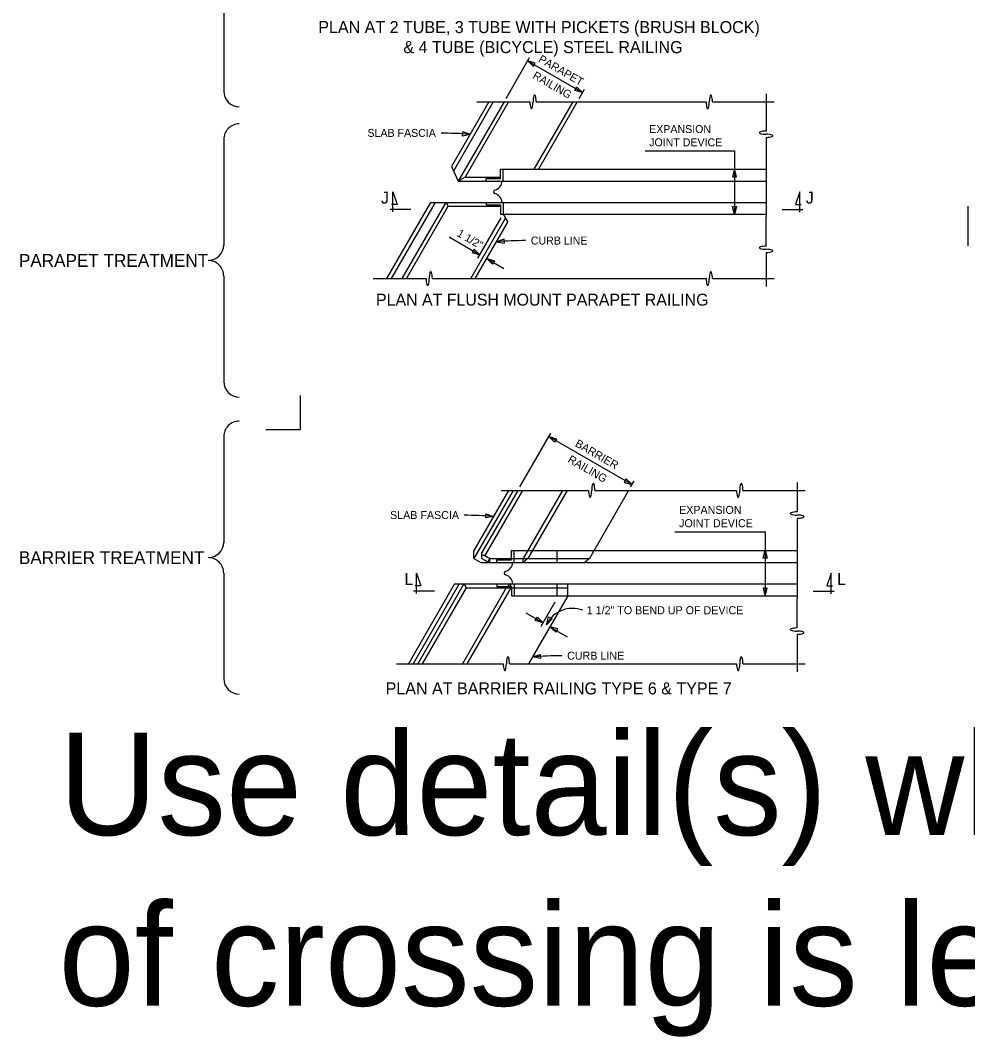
# Model space of a CAD drawing. Extents: x 19590 to 20151, y 19944 to 20103.
# Drawn here: x 19795.3 to 19850.6, y 19974.7 to 20034 of the extents above; entities that cross this region are included whole.
import ezdxf

# ---------------------------------------------------------------- set-up
doc = ezdxf.new("R2010")
doc.units = 0
for name, color, linetype in [('DETAIL_PR', 7, 'Continuous'), ('DETAIL_TEXT_DIMEN_PR', 7, 'Continuous'), ('Level 1', 7, 'Continuous')]:
    doc.layers.add(name, color=color, linetype=linetype)

msp = doc.modelspace()

# ---------------------------------------------------------------- linework, layer by layer
at = {"layer": 'DETAIL_PR'}
for p, q in [((19838.803, 20029.679), (19838.803, 20027.51)), ((19822.629, 20029.217), (19820.449, 20025.44)), ((19822.896, 20029.217), (19820.569, 20025.185)), ((19823.52, 20029.217), (19820.849, 20024.592)), ((19823.787, 20029.217), (19821.25, 20024.823)), ((19821.936, 20029.217), (19825.029, 20029.217)), ((19827.525, 20029.217), (19825.255, 20025.285)), ((19825.393, 20029.217), (19835.307, 20029.217)), ((19827.792, 20029.217), (19825.522, 20025.285)), ((19835.67, 20029.217), (19839.266, 20029.217)), ((19838.803, 20027.146), (19838.803, 20022.51)), ((19820.449, 20025.439), (19820.849, 20024.592)), ((19823.321, 20025.285), (19838.803, 20025.285)), ((19823.321, 20024.746), (19823.321, 20025.285)), ((19823.475, 20024.592), (19823.475, 20025.285)), ((19821.25, 20024.823), (19820.849, 20024.592)), ((19820.849, 20024.592), (19822.384, 20024.592)), ((19821.25, 20024.823), (19823.321, 20024.823)), ((19822.384, 20024.592), (19838.803, 20024.592)), ((19822.473, 20024.592), (19822.473, 20024.746)), ((19822.473, 20024.746), (19823.321, 20024.746)), ((19816.684, 20018.918), (19819.248, 20023.358)), ((19816.951, 20018.918), (19819.515, 20023.358)), ((19817.574, 20018.918), (19820.137, 20023.358)), ((19817.841, 20018.918), (19820.271, 20023.127)), ((19819.248, 20023.358), (19822.473, 20023.358)), ((19820.137, 20023.358), (19820.271, 20023.127)), ((19820.271, 20023.127), (19823.321, 20023.127)), ((19822.473, 20023.358), (19822.473, 20023.204)), ((19822.473, 20023.358), (19838.803, 20023.358)), ((19822.473, 20023.204), (19823.321, 20023.204)), ((19823.321, 20023.204), (19823.321, 20022.664)), ((19823.475, 20023.358), (19823.475, 20022.664)), ((19850.553, 20023.127), (19850.553, 20020.814)), ((19823.321, 20022.664), (19838.803, 20022.664)), ((19823.475, 20022.664), (19823.742, 20022.202)), ((19838.803, 20020.804), (19838.803, 20022.51)), ((19821.579, 20018.918), (19823.609, 20022.433)), ((19821.846, 20018.918), (19823.742, 20022.202)), ((19821.999, 20020.106), (19823.36, 20022.464)), ((19838.803, 20020.44), (19838.803, 20018.456)), ((19815.883, 20018.918), (19818.976, 20018.918)), ((19819.34, 20018.918), (19835.307, 20018.918)), ((19835.67, 20018.918), (19839.265, 20018.918)), ((19811.624, 20012.101), (19811.624, 20010.111)), ((19809.634, 20010.111), (19811.624, 20010.111)), ((19824.053, 20006.566), (19821.763, 20002.601)), ((19823.783, 20006.566), (19821.763, 20003.068)), ((19824.322, 20006.566), (19822.23, 20002.942)), ((19824.591, 20006.566), (19822.4, 20002.772)), ((19823.353, 20006.566), (19828.45, 20006.566)), ((19826.926, 20006.566), (19824.636, 20002.601)), ((19827.195, 20006.566), (19824.905, 20002.601)), ((19830.786, 20006.566), (19828.497, 20002.601)), ((19828.816, 20006.566), (19837.08, 20006.566)), ((19837.447, 20006.566), (19841.074, 20006.566)), ((19840.607, 20007.033), (19840.607, 20005.311)), ((19840.607, 20004.944), (19840.607, 20000.268)), ((19821.763, 20002.601), (19821.763, 20003.067)), ((19822.229, 20002.601), (19822.229, 20002.942)), ((19823.948, 20002.523), (19823.948, 20003.067)), ((19823.948, 20003.067), (19828.766, 20003.067)), ((19824.104, 20002.368), (19824.104, 20003.067)), ((19826.611, 20002.368), (19826.611, 20003.067)), ((19828.766, 20003.067), (19840.607, 20003.067)), ((19821.763, 20002.601), (19822.167, 20002.368)), ((19822.167, 20002.368), (19823.093, 20002.368)), ((19822.4, 20002.772), (19822.23, 20002.772)), ((19822.23, 20002.601), (19822.579, 20002.399)), ((19822.4, 20002.772), (19822.696, 20002.601)), ((19822.696, 20002.601), (19822.579, 20002.399)), ((19822.579, 20002.399), (19822.696, 20002.368)), ((19822.696, 20002.601), (19828.497, 20002.601)), ((19822.696, 20002.368), (19822.696, 20002.601)), ((19823.093, 20002.368), (19823.093, 20002.523)), ((19823.093, 20002.523), (19823.948, 20002.523)), ((19823.093, 20002.368), (19840.607, 20002.368)), ((19824.636, 20002.368), (19824.636, 20002.601)), ((19824.905, 20002.601), (19824.636, 20002.368)), ((19828.497, 20002.601), (19828.227, 20002.368)), ((19820.641, 20001.124), (19817.947, 19996.458)), ((19820.91, 20001.124), (19818.217, 19996.458)), ((19821.179, 20001.124), (19818.486, 19996.458)), ((19821.314, 20000.89), (19818.755, 19996.458)), ((19820.641, 20001.124), (19823.968, 20001.124)), ((19823.649, 20000.89), (19821.09, 19996.458)), ((19821.179, 20001.124), (19821.314, 20000.89)), ((19821.314, 20000.89), (19827.24, 20000.89)), ((19823.918, 20000.89), (19821.359, 19996.458)), ((19823.093, 20001.124), (19823.093, 20000.968)), ((19823.093, 20001.124), (19840.607, 20001.124)), ((19823.093, 20000.968), (19823.948, 20000.968)), ((19823.918, 20001.124), (19823.649, 20000.89)), ((19823.918, 20000.89), (19823.918, 20001.124)), ((19823.948, 20000.968), (19823.948, 20000.424)), ((19824.104, 20001.124), (19824.104, 20000.424)), ((19826.611, 20000.424), (19826.611, 20001.124)), ((19827.24, 20000.424), (19827.24, 20001.124)), ((19823.948, 20000.424), (19827.24, 20000.424)), ((19827.24, 20000.424), (19824.95, 19996.458)), ((19827.24, 20000.424), (19840.607, 20000.424)), ((19840.607, 19998.547), (19840.607, 20000.268)), ((19840.607, 19998.18), (19840.607, 19995.992)), ((19817.248, 19996.458), (19823.473, 19996.458)), ((19823.84, 19996.458), (19837.08, 19996.458)), ((19837.447, 19996.458), (19841.074, 19996.458))]:
    msp.add_line(p, q, dxfattribs=at)
for centre, radius, start, end in [((19822.799, 20024.656), 0.612, 288.13646, 353.93158), ((19822.997, 20023.975), 0.0999, 94.4387, 265.56132), ((19822.799, 20023.294), 0.612, 6.06842, 71.86353), ((19823.421, 20002.433), 0.618, 288.13646, 353.93158), ((19823.621, 20001.746), 0.101, 94.4387, 265.56132), ((19823.421, 20001.058), 0.618, 6.06842, 71.86353)]:
    msp.add_arc(centre, radius, start, end, dxfattribs=at)
for centre, major_axis, ratio, start_param, end_param in [((19825.302, 20029.217), (0, -0.395), 0.230204, 1.570796, 4.712389), ((19835.579, 20029.217), (0, -0.395), 0.230204, 1.570796, 4.712389), ((19825.12, 20029.217), (0, -0.395), 0.230206, 4.712389, 7.853982), ((19835.397, 20029.217), (0, -0.395), 0.230206, 4.712389, 7.853982), ((19838.803, 20027.419), (0.395, 0), 0.230204, 1.570796, 4.712389), ((19838.803, 20027.237), (0.395, 0), 0.230206, 4.712389, 7.853982), ((19838.803, 20020.713), (0.395, 0), 0.230204, 1.570796, 4.712389), ((19838.803, 20020.531), (0.395, 0), 0.230206, 4.712389, 7.853982), ((19819.249, 20018.918), (0, -0.395), 0.230204, 1.570796, 4.712389), ((19835.579, 20018.918), (0, -0.395), 0.230204, 1.570796, 4.712389), ((19819.067, 20018.918), (0, -0.395), 0.230206, 4.712389, 7.853982), ((19835.397, 20018.918), (0, -0.395), 0.230206, 4.712389, 7.853982), ((19828.541, 20006.566), (0, -0.398), 0.230206, 4.712389, 7.853982), ((19828.725, 20006.566), (0, -0.398), 0.230204, 1.570796, 4.712389), ((19837.172, 20006.566), (0, -0.398), 0.230206, 4.712389, 7.853982), ((19837.356, 20006.566), (0, -0.398), 0.230204, 1.570796, 4.712389), ((19840.607, 20005.22), (0.398, 0), 0.230204, 1.570796, 4.712389), ((19840.607, 20005.036), (0.398, 0), 0.230206, 4.712389, 7.853982), ((19840.607, 19998.455), (0.398, 0), 0.230204, 1.570796, 4.712389), ((19840.607, 19998.272), (0.398, 0), 0.230206, 4.712389, 7.853982), ((19823.565, 19996.458), (0, -0.398), 0.230206, 4.712389, 7.853982), ((19823.748, 19996.458), (0, -0.398), 0.230204, 1.570796, 4.712389), ((19837.172, 19996.458), (0, -0.398), 0.230206, 4.712389, 7.853982), ((19837.356, 19996.458), (0, -0.398), 0.230204, 1.570796, 4.712389)]:
    msp.add_ellipse(centre, major_axis=major_axis, ratio=ratio, start_param=start_param, end_param=end_param, dxfattribs=at)
at = {"layer": 'DETAIL_TEXT_DIMEN_PR'}
for p, q in [((19807.176, 20035.98), (19807.176, 20029.838)), ((19823.635, 20029.417), (19825.014, 20031.806)), ((19824.898, 20031.606), (19828.103, 20029.755)), ((19827.907, 20029.417), (19828.218, 20029.956)), ((19807.176, 20027.022), (19807.176, 20020.837)), ((19831.741, 20026.364), (19836.953, 20026.364)), ((19836.953, 20026.364), (19836.953, 20022.664)), ((19817.038, 20022.804), (19817.037, 20023.975)), ((19817.037, 20023.975), (19817.29, 20023.239)), ((19840.768, 20023.975), (19840.515, 20023.239)), ((19840.768, 20022.777), (19840.768, 20023.975)), ((19817.29, 20023.239), (19816.96, 20023.239)), ((19840.515, 20023.239), (19840.846, 20023.239)), ((19818.078, 20022.934), (19816.872, 20022.934)), ((19839.728, 20022.934), (19840.943, 20022.934)), ((19820.312, 20021.348), (19822.114, 20020.307)), ((19822.515, 20020.076), (19823.516, 20019.498)), ((19807.176, 20019.061), (19807.176, 20012.919)), ((19807.176, 20009.698), (19807.176, 20003.514)), ((19824.438, 20006.769), (19826.252, 20009.909)), ((19826.135, 20009.707), (19830.983, 20006.908)), ((19830.903, 20006.769), (19831.1, 20007.11)), ((19833.484, 20004.156), (19838.741, 20004.156)), ((19838.741, 20004.156), (19838.741, 20000.424)), ((19807.176, 20001.737), (19807.176, 19995.595)), ((19818.412, 20000.564), (19818.411, 20001.746)), ((19818.411, 20001.746), (19818.666, 20001.003)), ((19842.59, 20001.746), (19842.335, 20001.003)), ((19842.589, 20000.537), (19842.59, 20001.746)), ((19819.461, 20000.696), (19818.244, 20000.696)), ((19818.666, 20001.003), (19818.333, 20001.003)), ((19841.54, 20000.696), (19842.766, 20000.696)), ((19842.335, 20001.003), (19842.668, 20001.003)), ((19825.678, 19998.652), (19826.495, 20000.066)), ((19824.785, 19999.438), (19825.795, 19998.855)), ((19826.199, 19998.621), (19827.209, 19998.038))]:
    msp.add_line(p, q, dxfattribs=at)
for centre, radius, start, end in [((19808.086, 20029.839), 0.91, 180.03373, 270.03369), ((19808.086, 20027.022), 0.91, 89.96627, 180.03372), ((19819.112, 19988.252), 39.151, 86.44645, 88.92222), ((19806.266, 20020.881), 0.911, 269.96631, 359.96626), ((19825.511, 19981.986), 39.151, 91.07778, 93.55355), ((19806.266, 20019.061), 0.91, 359.96627, 90.03372), ((19808.086, 20012.92), 0.91, 180.03373, 270.03369), ((19808.086, 20009.699), 0.91, 89.96627, 180.03372), ((19820.46, 19965.634), 39.492, 86.44645, 88.92222), ((19806.266, 20003.558), 0.911, 269.96631, 359.96626), ((19806.266, 20001.737), 0.91, 359.96627, 90.03372), ((19827.511, 19998.012), 1.679, 69.13778, 154.38451), ((19827.631, 19957.446), 39.492, 91.07778, 93.55355), ((19808.086, 19995.596), 0.91, 180.03373, 270.03369)]:
    msp.add_arc(centre, radius, start, end, dxfattribs=at)
at = {"layer": 'Level 1'}
for p, q in [((19824.899, 20031.605), (19825.229, 20031.281)), ((19825.344, 20031.481), (19824.899, 20031.605)), ((19825.229, 20031.281), (19825.344, 20031.481)), ((19827.657, 20029.879), (19827.773, 20030.079)), ((19828.103, 20029.755), (19827.657, 20029.879)), ((19827.773, 20030.079), (19828.103, 20029.755)), ((19821.098, 20027.468), (19821.085, 20027.237)), ((19821.085, 20027.237), (19821.539, 20027.328)), ((19821.539, 20027.328), (19821.098, 20027.468)), ((19836.953, 20025.285), (19836.837, 20024.838)), ((19837.069, 20024.838), (19836.953, 20025.285)), ((19836.837, 20024.838), (19837.069, 20024.838)), ((19836.953, 20022.664), (19836.837, 20023.112)), ((19836.837, 20023.112), (19837.068, 20023.112)), ((19837.068, 20023.112), (19836.953, 20022.664)), ((19823.525, 20021.202), (19823.084, 20021.062)), ((19823.084, 20021.062), (19823.538, 20020.971)), ((19823.538, 20020.971), (19823.525, 20021.202)), ((19821.784, 20020.631), (19821.668, 20020.43)), ((19821.668, 20020.43), (19822.114, 20020.306)), ((19822.114, 20020.306), (19821.784, 20020.631)), ((19822.515, 20020.076), (19822.96, 20019.952)), ((19822.845, 20019.751), (19822.515, 20020.076)), ((19822.96, 20019.952), (19822.845, 20019.751)), ((19826.135, 20009.707), (19826.585, 20009.582)), ((19826.468, 20009.38), (19826.135, 20009.707)), ((19826.585, 20009.582), (19826.468, 20009.38)), ((19830.65, 20007.235), (19830.534, 20007.033)), ((19830.984, 20006.908), (19830.65, 20007.235)), ((19830.534, 20007.033), (19830.984, 20006.908)), ((19822.45, 20004.959), (19822.463, 20005.192)), ((19822.908, 20005.05), (19822.45, 20004.959)), ((19822.463, 20005.192), (19822.908, 20005.05)), ((19838.624, 20002.616), (19838.741, 20003.067)), ((19838.741, 20003.067), (19838.858, 20002.616)), ((19838.858, 20002.616), (19838.624, 20002.616)), ((19838.858, 20000.875), (19838.624, 20000.875)), ((19838.624, 20000.875), (19838.741, 20000.424)), ((19838.741, 20000.424), (19838.858, 20000.875)), ((19825.345, 19998.979), (19825.462, 19999.182)), ((19825.795, 19998.854), (19825.345, 19998.979)), ((19825.462, 19999.182), (19825.795, 19998.854)), ((19825.997, 19998.738), (19826.122, 19999.188)), ((19826.324, 19999.071), (19825.997, 19998.738)), ((19826.122, 19999.188), (19826.324, 19999.071)), ((19826.199, 19998.621), (19826.532, 19998.295)), ((19826.648, 19998.497), (19826.199, 19998.621)), ((19826.532, 19998.295), (19826.648, 19998.497)), ((19825.184, 19996.862), (19825.629, 19997.004)), ((19825.641, 19996.771), (19825.184, 19996.862)), ((19825.629, 19997.004), (19825.641, 19996.771))]:
    msp.add_line(p, q, dxfattribs=at)

# ---------------------------------------------------------------- texts
at = {"layer": 'DETAIL_TEXT_DIMEN_PR'}
for s, height, p in [('PLAN AT 2 TUBE, 3 TUBE WITH PICKETS (BRUSH BLOCK)', 0.69987, (19812.691, 20033.224)), (' & 4 TUBE (BICYCLE) STEEL RAILING', 0.69987, (19817.394, 20032.058)), ('EXPANSION ', 0.4625, (19831.982, 20027.398)), ('SLAB FASCIA', 0.4625, (19815.559, 20027.177)), ('JOINT DEVICE', 0.4625, (19831.982, 20026.627)), ('J', 0.694, (19816.343, 20023.282)), ('J', 0.694, (19841.115, 20023.281)), ('CURB LINE', 0.4625, (19825.083, 20020.899)), ('PLAN AT FLUSH MOUNT PARAPET RAILING', 0.69385, (19816.056, 20017.336)), ('SLAB FASCIA', 0.46653, (19816.875, 20004.898)), ('EXPANSION ', 0.4665, (19833.727, 20005.198)), ('JOINT DEVICE', 0.46653, (19833.727, 20004.421)), ('L', 0.7, (19817.712, 20001.046)), ('L', 0.7, (19842.94, 20001.046)), ('1 1/2" TO BEND UP OF DEVICE', 0.46653, (19828.343, 19999.348)), ('CURB LINE', 0.4665, (19827.2, 19996.699)), ('PLAN AT BARRIER RAILING TYPE 6 & TYPE 7', 0.69989, (19816.616, 19994.675)), ('Use detail(s) when angle(s) ', 5.97143, (19797.549, 19986.475)), ('of crossing is less than 70', 5.97143, (19797.549, 19976.523))]:
    msp.add_text(s, height=height, dxfattribs=at).set_placement(p)
for s, height, rotation, p in [('PARAPET', 0.4625, 330, (19825.483, 20031.579)), ('RAILING', 0.4625, 330, (19825.148, 20030.616)), ('1 1/2"', 0.4625, 330, (19820.731, 20021.418)), ('PARAPET TREATMENT', 0.74643, 360, (19795.235, 20019.597)), ('BARRIER', 0.4665, 330, (19827.62, 20009.164)), ('RAILING', 0.4665, 330, (19827.195, 20008.242)), ('BARRIER TREATMENT', 0.74643, 360, (19795.235, 20002.274))]:
    msp.add_text(s, height=height, rotation=rotation, dxfattribs=at).set_placement(p)

doc.saveas('drawing.dxf')
